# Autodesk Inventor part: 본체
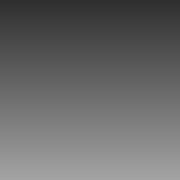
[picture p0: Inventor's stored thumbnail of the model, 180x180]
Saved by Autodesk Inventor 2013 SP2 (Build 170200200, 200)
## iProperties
Created: 2024-07
Part Number: 본체
Material: Generic
Document SubType Name: Modeling
Designer: a
Density: 1 g/cm^3
Author: a
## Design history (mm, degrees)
